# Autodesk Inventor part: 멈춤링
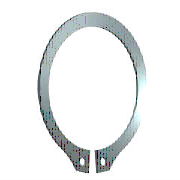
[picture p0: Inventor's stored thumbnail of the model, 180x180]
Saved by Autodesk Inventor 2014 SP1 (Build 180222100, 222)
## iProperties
IsCustomPart: 0
Created: 2009-02
Part Number: 멈춤링
Material: 강, 연강
Description: 리테이닝 링(C형)
Document SubType Name: Modeling
Standard: KS B 1336
Designer: KYOUNG IL JANG
Standards Organization: KS
Language: ko-KR
Size Designation: 22 x 1.2
Categories: <MemberInstance><Categories><Category DisplayName="샤프트 부품" InternalName="7f7aeb1f-a693-4053-b835-cee3144e0d98" Mnemonic="SHFT"><Category DisplayName="써클립" Inter
Density: 1 g/cm^3
Appearance: 강철
Author: KYOUNG IL JANG
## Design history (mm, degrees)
sketch "스케치1"
  geometry: L1 (-6, 0)-(6, 0) reference; L2 (0, 20.189)-(0, -80.536) reference; L3 (-48.09, 0)-(48.09, 0) reference; L4 (-0.5, -21.488)-(-0.5, -25.588); L5 (-0.5, -6.54)-(-0.5, -13.29); L6 (-2.795, 2.7)-(3.672, 2.7); L7 (0.5, -6.54)-(0.5, -13.29); L8 (0.5, -21.488)-(0.5, -25.588); C1 r 1 at (-2, -23.437); C2 r 1 at (2, -23.437); A1 r 10.5 centre (0, -11) between (0.5, -21.488) and (-0.5, -21.488); A2 r 13.025 centre (0, -10.325) between (5.149, -22.289) and (-5.149, -22.289); A3 r 14.597 centre (0, -11) between (-2.318, -25.411) and (-0.5, -25.588); A4 r 2 centre (-2, -23.437) between (-3.97, -23.781) and (-2.318, -25.411); A5 r 2 centre (-5.94, -24.126) between (-3.97, -23.781) and (-5.149, -22.289); A6 r 2 centre (5.94, -24.126) between (5.149, -22.289) and (3.97, -23.781); A7 r 2 centre (2, -23.437) between (2.318, -25.411) and (3.97, -23.781); A8 r 14.597 centre (0, -11) between (0.5, -25.588) and (2.318, -25.411)
  constraints: 16 point on circle, 12 end point, 10 centre point, 9 symmetric about line, 5 point on line, 4 tangent, 3 coincident, 2 horizontal, 1 perpendicular, 1 vertical, 5 other
  dimensions: "d0" = 21 diameter of A1 (= ND); "d1" = 4.1 distance of L4.end L4.start (= SRB2); "d6" = 0.5 distance between parallel lines of L2 L5 (= 0.25 x SD5); "d7" = 2.7 distance between parallel lines of L6 L3 (= SRB1); "d8" = 0.675 distance of A1.centre A2.centre (= 0.25 x SRB1); "d9" = 2 radius of A4 (= SD5); "d10" = 2 radius of A5 (= SD5); "d11" = 1.5 distance from line of L4 A4.centre (= 0.75 x SD5); "d12" = 2 diameter of C1 (= SD5); "d13" = 2 diameter of C2 (= SD5); "d14" = 11 distance from line of A1.centre L1 (= 0.5 x WD)
extrude "본체" new body sketch "스케치1" distance "d2" = 1.2 (= SD); taper "d3" = 0 deg
workaxis "Work Axis1"
workplane "Work Plane1"
body "Solid1"
other parameters: "WD" = 22 (= WDMIN) [user parameter; used in 1 equation term], "SD" = 1.2 [user parameter; used in 1 equation term], "SRB1" = 2.7 [user parameter; used in 2 equation terms], "ND" = 21 [user parameter; used in 1 equation term], "SRB2" = 4.1 [user parameter; used in 1 equation term], "SD5" = 2 [user parameter; used in 6 equation terms], "d15" = 0, "d16" = 0, "d17" = 0, "d41" = 0, "d42" = 0, "WDMIN" = 22 [user parameter; used in 1 equation term], "SD3" = 20.5 [user parameter], "WDMAX" = 24 [user parameter]
